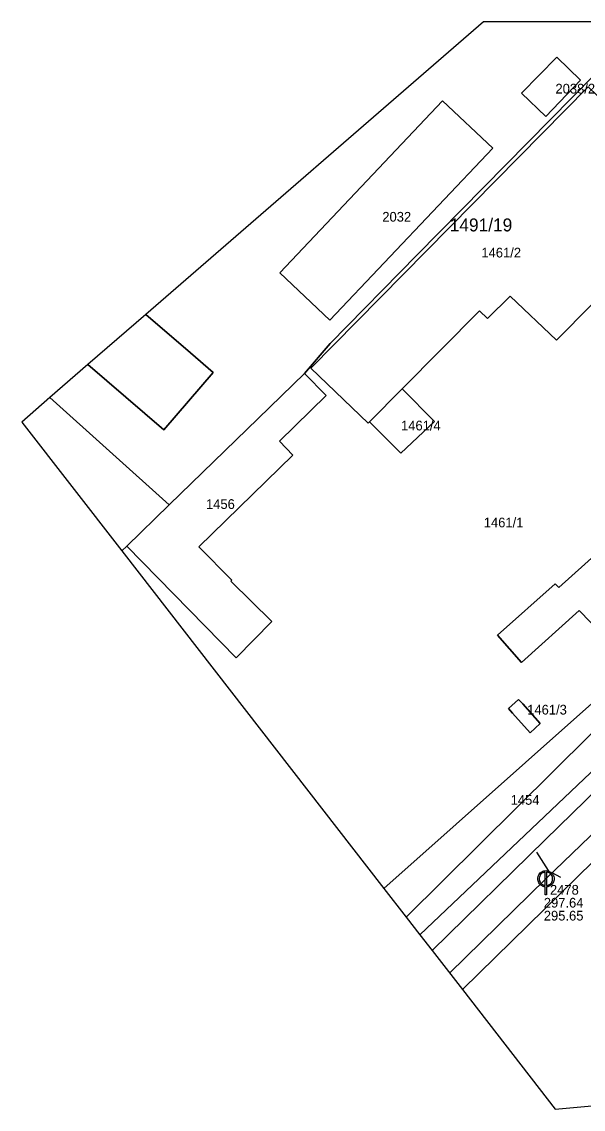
# Model space of a CAD drawing. Extents: x -570890 to -570546, y -1086481 to -1086296.
# Drawn here: x -570890.1 to -570803.2, y -1086463.9 to -1086295.8 of the extents above; entities that cross this region are included whole.
import ezdxf

# ---------------------------------------------------------------- set-up
doc = ezdxf.new("R2010")
doc.units = 0
for name, color, linetype in [('Adresní místo-text', 7, 'Continuous'), ('Default', 7, 'Continuous'), ('Kanalizační přípojka', 7, 'Continuous'), ('Kanalizační stoka', 7, 'Continuous'), ('Kanalizační šachta', 7, 'Continuous'), ('Parcela-polygon', 7, 'Continuous'), ('Parcela-text', 7, 'Continuous'), ('Popis šachty', 7, 'Continuous')]:
    doc.layers.add(name, color=color, linetype=linetype)

msp = doc.modelspace()

# ---------------------------------------------------------------- linework, layer by layer
at = {"layer": 'Default'}
for points in [[(-570809.1, -1086429.53), (-570809.36, -1086429.51), (-570809.62, -1086429.36), (-570809.92, -1086429.2), (-570810.09, -1086428.9), (-570810.25, -1086428.6), (-570810.25, -1086428.28), (-570810.25, -1086427.95), (-570810.08, -1086427.65), (-570809.91, -1086427.35), (-570809.62, -1086427.19), (-570809.32, -1086427.03), (-570809, -1086427.03), (-570808.69, -1086427.03), (-570808.39, -1086427.19), (-570808.09, -1086427.35), (-570807.92, -1086427.65), (-570807.75, -1086427.95), (-570807.75, -1086428.28), (-570807.75, -1086428.6), (-570807.91, -1086428.9), (-570808.08, -1086429.2), (-570808.38, -1086429.36), (-570808.64, -1086429.51), (-570808.9, -1086429.53)], [(-570809.1, -1086427.24), (-570809.3, -1086427.26), (-570809.52, -1086427.37), (-570809.76, -1086427.51), (-570809.9, -1086427.76), (-570810.04, -1086428.01), (-570810.04, -1086428.28), (-570810.04, -1086428.55), (-570809.91, -1086428.8), (-570809.77, -1086429.04), (-570809.52, -1086429.18), (-570809.31, -1086429.3), (-570809.1, -1086429.32)], [(-570808.9, -1086429.32), (-570808.69, -1086429.3), (-570808.48, -1086429.18), (-570808.23, -1086429.04), (-570808.09, -1086428.8), (-570807.96, -1086428.55), (-570807.96, -1086428.28), (-570807.96, -1086428.01), (-570808.1, -1086427.76), (-570808.24, -1086427.51), (-570808.49, -1086427.37), (-570808.7, -1086427.26), (-570808.9, -1086427.24)]]:
    msp.add_open_spline(points, degree=3, dxfattribs=at)
at = {"layer": 'Kanalizační přípojka'}
for points in [[(-570810.47, -1086424.17), (-570808.28, -1086427.59)], [(-570806.72, -1086428.11), (-570808.06, -1086427.38)]]:
    msp.add_lwpolyline(points, dxfattribs=at)
at = {"layer": 'Kanalizační stoka'}
for points in [[(-570779.07, -1086399.53), (-570794.04, -1086413.91), (-570809, -1086428.28)], [(-570809, -1086428.28), (-570823.9, -1086442.88)]]:
    msp.add_lwpolyline(points, dxfattribs=at)
at = {"layer": 'Kanalizační šachta'}
for points in [[(-570809.1, -1086429.32), (-570809.1, -1086427.24)], [(-570808.9, -1086427.24), (-570808.9, -1086429.32)], [(-570808.9, -1086429.53), (-570808.9, -1086430.78), (-570809.1, -1086430.78), (-570809.1, -1086429.53)]]:
    msp.add_lwpolyline(points, dxfattribs=at)
at = {"layer": 'Parcela-polygon'}
for p, q in [((-570870.92, -1086341.04), (-570879.87, -1086348.79)), ((-570879.87, -1086348.79), (-570885.76, -1086353.89)), ((-570874.64, -1086377.57), (-570834.09, -1086429.77)), ((-570834.09, -1086429.77), (-570830.62, -1086434.23)), ((-570830.62, -1086434.23), (-570828.49, -1086436.97)), ((-570828.49, -1086436.97), (-570826.6, -1086439.4)), ((-570826.6, -1086439.4), (-570821.92, -1086445.43))]:
    msp.add_line(p, q, dxfattribs=at)
for points in [[(-570885.76, -1086353.89), (-570867.3, -1086370.48), (-570853.55, -1086357.1), (-570846.35, -1086350.15), (-570842.37, -1086345.54), (-570828.93, -1086331.81), (-570801.51, -1086303.97), (-570796.56, -1086298.95), (-570797.47, -1086298.1), (-570799.94, -1086295.77)], [(-570799.94, -1086295.77), (-570818.64, -1086295.77), (-570870.92, -1086341.04)], [(-570812.77, -1086306.84), (-570807.33, -1086301.25), (-570803.67, -1086304.82), (-570809, -1086310.41), (-570812.77, -1086306.84)], [(-570834.09, -1086429.77), (-570756.68, -1086361), (-570756.34, -1086360.67), (-570756.02, -1086355.74), (-570754.01, -1086353.82), (-570801.51, -1086303.97), (-570828.93, -1086331.81), (-570842.37, -1086345.54), (-570846.35, -1086350.15), (-570843.03, -1086353.56), (-570850.23, -1086360.64), (-570848.15, -1086362.79), (-570862.71, -1086376.95), (-570857.62, -1086382.09), (-570857.78, -1086382.29), (-570851.41, -1086388.5), (-570856.93, -1086394.12), (-570873.87, -1086376.88), (-570874.64, -1086377.57)], [(-570845.38, -1086349.32), (-570802.45, -1086305.82), (-570793.61, -1086314.41), (-570785.42, -1086322.83), (-570807.36, -1086345.01), (-570814.52, -1086338.18), (-570818.02, -1086341.66), (-570819.26, -1086340.47), (-570831.24, -1086352.51), (-570826.25, -1086357.59), (-570831.43, -1086362.48), (-570836.32, -1086357.65), (-570836.49, -1086357.82), (-570845.38, -1086349.32)], [(-570704.56, -1086305.59), (-570706.17, -1086307.5), (-570707.16, -1086308.58), (-570707.13, -1086309.53), (-570707.29, -1086311.56), (-570707.81, -1086313.54), (-570709.31, -1086316.22), (-570714.9, -1086323.38), (-570723.45, -1086333.39), (-570738.16, -1086351.15), (-570747.27, -1086361.72), (-570767.99, -1086382.05), (-570788.27, -1086401.95), (-570809.12, -1086422.25), (-570826.6, -1086439.4)], [(-570817.21, -1086315.34), (-570842.46, -1086341.89), (-570850.17, -1086334.61), (-570825.03, -1086308.01), (-570817.21, -1086315.34)], [(-570826.6, -1086439.4), (-570809.12, -1086422.25), (-570788.27, -1086401.95), (-570767.99, -1086382.05), (-570747.27, -1086361.72), (-570738.16, -1086351.15), (-570723.45, -1086333.39), (-570714.9, -1086323.38), (-570709.31, -1086316.22), (-570707.81, -1086313.54), (-570707.29, -1086311.56), (-570707.13, -1086309.53), (-570707.16, -1086308.58), (-570740.99, -1086345.46), (-570751.79, -1086356.16), (-570752.3, -1086356.66), (-570750.1, -1086358.88), (-570767.56, -1086379.15), (-570828.49, -1086436.97)], [(-570821.92, -1086445.43), (-570778.82, -1086403.26), (-570763.09, -1086387.87), (-570764.01, -1086386.9), (-570761.96, -1086384.93), (-570742.89, -1086365.83), (-570730.22, -1086351.07), (-570727.69, -1086353.18), (-570725.54, -1086350.6), (-570715.91, -1086339.05), (-570710.14, -1086332.11), (-570695.97, -1086315.11), (-570689.45, -1086307.51)], [(-570789.21, -1086333.9), (-570781.72, -1086326.7), (-570771.31, -1086337.28), (-570771.53, -1086337.5), (-570761.89, -1086347.32), (-570755.87, -1086353.47), (-570761.86, -1086359.31), (-570773.1, -1086370.2), (-570771.53, -1086371.82), (-570788.19, -1086386.62), (-570796.69, -1086394.15), (-570803.85, -1086386.79), (-570812.78, -1086394.83), (-570816.48, -1086390.61), (-570807.55, -1086382.66), (-570807.02, -1086383.24), (-570798.47, -1086375.55), (-570795.84, -1086378.45), (-570779.1, -1086364.02), (-570769.21, -1086354.43), (-570789.21, -1086333.9)], [(-570879.87, -1086348.79), (-570868.14, -1086358.87), (-570860.51, -1086350), (-570864.02, -1086346.97), (-570870.92, -1086341.04)], [(-570870.92, -1086341.04), (-570864.02, -1086346.97), (-570860.51, -1086350), (-570868.14, -1086358.87), (-570879.87, -1086348.79)], [(-570885.76, -1086353.89), (-570890.11, -1086357.66), (-570874.64, -1086377.57)], [(-570874.64, -1086377.57), (-570873.87, -1086376.88), (-570867.3, -1086370.48), (-570885.76, -1086353.89)], [(-570828.49, -1086436.97), (-570767.56, -1086379.15), (-570750.1, -1086358.88), (-570752.3, -1086356.66), (-570756.34, -1086360.67), (-570756.68, -1086361), (-570830.62, -1086434.23)], [(-570830.62, -1086434.23), (-570756.68, -1086361), (-570834.09, -1086429.77)], [(-570813.26, -1086400.55), (-570812.6, -1086401.23), (-570809.87, -1086404.28), (-570811.46, -1086405.72), (-570814.19, -1086402.67), (-570814.81, -1086401.94), (-570813.26, -1086400.55)], [(-570793.46, -1086462.61), (-570769.59, -1086433.84), (-570759.06, -1086423.52), (-570773.55, -1086408.66), (-570778.82, -1086403.26), (-570821.92, -1086445.43)], [(-570821.92, -1086445.43), (-570807.55, -1086463.92), (-570793.46, -1086462.61)]]:
    msp.add_lwpolyline(points, dxfattribs=at)
for points in [[(-570812.77, -1086306.84), (-570809, -1086310.41), (-570803.67, -1086304.82), (-570807.33, -1086301.25)], [(-570845.38, -1086349.32), (-570836.49, -1086357.82), (-570836.32, -1086357.65), (-570831.24, -1086352.51), (-570819.26, -1086340.47), (-570818.02, -1086341.66), (-570814.52, -1086338.18), (-570807.36, -1086345.01), (-570785.42, -1086322.83), (-570793.61, -1086314.41), (-570802.45, -1086305.82)], [(-570825.03, -1086308.01), (-570850.17, -1086334.61), (-570842.46, -1086341.89), (-570817.21, -1086315.34)], [(-570846.35, -1086350.15), (-570853.55, -1086357.1), (-570867.3, -1086370.48), (-570873.87, -1086376.88), (-570856.93, -1086394.12), (-570851.41, -1086388.5), (-570857.78, -1086382.29), (-570857.62, -1086382.09), (-570862.71, -1086376.95), (-570848.15, -1086362.79), (-570850.23, -1086360.64), (-570843.03, -1086353.56)], [(-570831.24, -1086352.51), (-570836.32, -1086357.65), (-570831.43, -1086362.48), (-570826.25, -1086357.59)], [(-570795.84, -1086378.45), (-570798.47, -1086375.55), (-570807.02, -1086383.24), (-570807.55, -1086382.66), (-570816.48, -1086390.61), (-570812.78, -1086394.83), (-570803.85, -1086386.79), (-570796.69, -1086394.15), (-570788.19, -1086386.62), (-570771.53, -1086371.82), (-570773.1, -1086370.2), (-570779.1, -1086364.02)], [(-570813.26, -1086400.55), (-570814.81, -1086401.94), (-570814.19, -1086402.67), (-570811.46, -1086405.72), (-570809.87, -1086404.28), (-570812.6, -1086401.23)]]:
    msp.add_lwpolyline(points, close=True, dxfattribs=at)

# ---------------------------------------------------------------- texts
at = {"layer": 'Adresní místo-text'}
msp.add_text('1491/19', height=2, dxfattribs=at).set_placement((-570823.88, -1086328.19))
at = {"layer": 'Parcela-text'}
for s, p in [('2038/2', (-570807.53, -1086306.87)), ('2032', (-570834.32, -1086326.68)), ('1461/2', (-570818.99, -1086332.22)), ('1461/4', (-570831.42, -1086358.96)), ('1456', (-570861.6, -1086371.1)), ('1461/1', (-570818.62, -1086373.95)), ('1461/3', (-570811.9, -1086402.89)), ('1454', (-570814.46, -1086416.84))]:
    msp.add_text(s, height=1.5, dxfattribs=at).set_placement(p)
at = {"layer": 'Popis šachty'}
for s, p in [('2478', (-570808.38, -1086430.74)), ('297.64', (-570809.33, -1086432.74)), ('295.65', (-570809.33, -1086434.74))]:
    msp.add_text(s, height=1.5, dxfattribs=at).set_placement(p)

doc.saveas('drawing.dxf')
